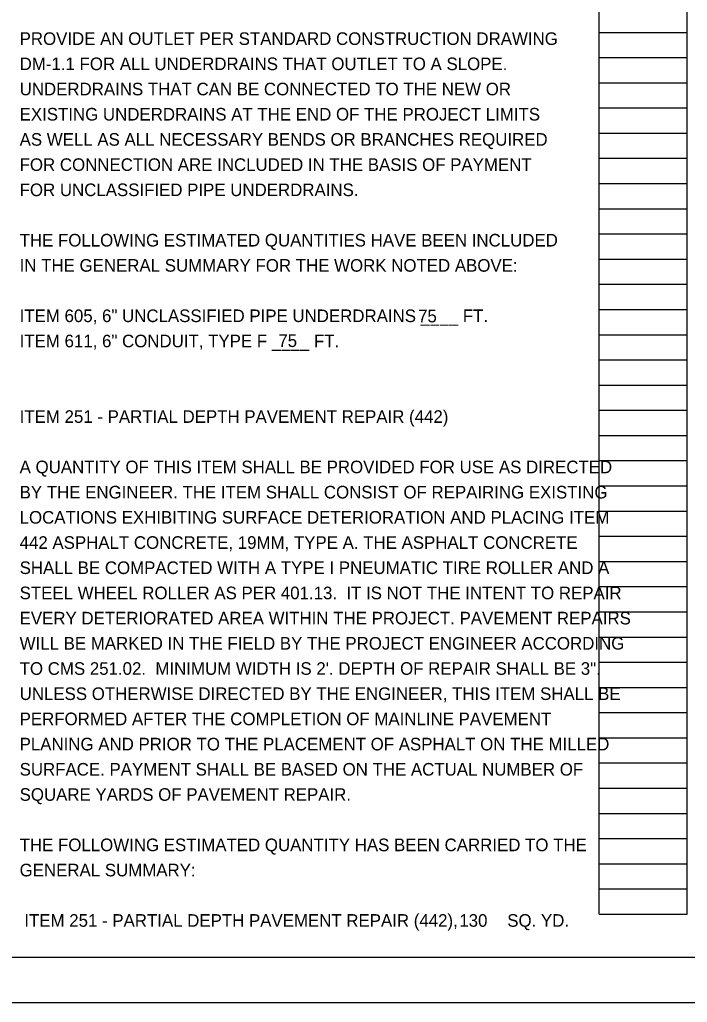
# Model space of a CAD drawing. Extents: x 0 to 74, y -27.6 to 51.8.
# Drawn here: x 17.24 to 24.66, y 0 to 10.92 of the extents above; entities that cross this region are included whole.
import ezdxf

# ---------------------------------------------------------------- set-up
doc = ezdxf.new("R2010")
doc.units = 0
for name, color, linetype in [('Level 1', 7, 'Continuous'), ('Level 2', 7, 'Continuous'), ('Level 3', 7, 'Continuous'), ('Level 4', 7, 'Continuous')]:
    doc.layers.add(name, color=color, linetype=linetype)

msp = doc.modelspace()

# ---------------------------------------------------------------- linework, layer by layer
at = {"layer": 'Level 1'}
msp.add_lwpolyline([(0, 0), (34, 0), (34, 22), (0, 22)], close=True, dxfattribs=at)
at = {"layer": 'Level 2'}
msp.add_lwpolyline([(1.5, 21.5), (33.5, 21.5), (33.5, 0.5), (1.5, 0.5)], close=True, dxfattribs=at)
at = {"layer": 'Level 3'}
for p, q in [((23.68, 0.98), (23.68, 21.14)), ((24.66, 0.98), (24.66, 21.14)), ((23.68, 10.78), (24.66, 10.78)), ((23.68, 10.5), (24.66, 10.5)), ((23.68, 10.22), (24.66, 10.22)), ((23.68, 9.94), (24.66, 9.94)), ((23.68, 9.66), (24.66, 9.66)), ((23.68, 9.38), (24.66, 9.38)), ((23.68, 9.1), (24.66, 9.1)), ((23.68, 8.82), (24.66, 8.82)), ((23.68, 8.54), (24.66, 8.54)), ((23.68, 8.26), (24.66, 8.26)), ((23.68, 7.98), (24.66, 7.98)), ((23.68, 7.7), (24.66, 7.7)), ((23.68, 7.42), (24.66, 7.42)), ((23.68, 7.14), (24.66, 7.14)), ((23.68, 6.86), (24.66, 6.86)), ((23.68, 6.58), (24.66, 6.58)), ((23.68, 6.3), (24.66, 6.3)), ((23.68, 6.02), (24.66, 6.02)), ((23.68, 5.74), (24.66, 5.74)), ((23.68, 5.46), (24.66, 5.46)), ((23.68, 5.18), (24.66, 5.18)), ((23.68, 4.9), (24.66, 4.9)), ((23.68, 4.62), (24.66, 4.62)), ((23.68, 4.34), (24.66, 4.34)), ((23.68, 4.06), (24.66, 4.06)), ((23.68, 3.78), (24.66, 3.78)), ((23.68, 3.5), (24.66, 3.5)), ((23.68, 3.22), (24.66, 3.22)), ((23.68, 2.94), (24.66, 2.94)), ((23.68, 2.66), (24.66, 2.66)), ((23.68, 2.38), (24.66, 2.38)), ((23.68, 2.1), (24.66, 2.1)), ((23.68, 1.82), (24.66, 1.82)), ((23.68, 1.54), (24.66, 1.54)), ((23.68, 1.26), (24.66, 1.26)), ((23.68, 0.98), (24.66, 0.98))]:
    msp.add_line(p, q, dxfattribs=at)

# ---------------------------------------------------------------- texts
at = {"layer": 'Level 4'}
for s, p in [('PROVIDE AN OUTLET PER STANDARD CONSTRUCTION DRAWING', (17.24, 10.64)), ('DM-1.1 FOR ALL UNDERDRAINS THAT OUTLET TO A SLOPE.', (17.24, 10.36)), ('UNDERDRAINS THAT CAN BE CONNECTED TO THE NEW OR', (17.24, 10.08)), ('EXISTING UNDERDRAINS AT THE END OF THE PROJECT LIMITS', (17.24, 9.8)), ('AS WELL AS ALL NECESSARY BENDS OR BRANCHES REQUIRED', (17.24, 9.52)), ('FOR CONNECTION ARE INCLUDED IN THE BASIS OF PAYMENT', (17.24, 9.24)), ('FOR UNCLASSIFIED PIPE UNDERDRAINS.', (17.24, 8.96)), ('THE FOLLOWING ESTIMATED QUANTITIES HAVE BEEN INCLUDED', (17.24, 8.4)), ('IN THE GENERAL SUMMARY FOR THE WORK NOTED ABOVE:', (17.24, 8.12)), ('ITEM 605, 6" UNCLASSIFIED PIPE UNDERDRAINS ____ FT.', (17.24, 7.56)), ('75', (21.668, 7.557)), ('ITEM 611, 6" CONDUIT, TYPE F ____ FT.', (17.24, 7.28)), ('75', (20.115, 7.283)), ('ITEM 251 - PARTIAL DEPTH PAVEMENT REPAIR (442)', (17.24, 6.44)), ('A QUANTITY OF THIS ITEM SHALL BE PROVIDED FOR USE AS DIRECTED ', (17.24, 5.88)), ('BY THE ENGINEER. THE ITEM SHALL CONSIST OF REPAIRING EXISTING ', (17.24, 5.6)), ('LOCATIONS EXHIBITING SURFACE DETERIORATION AND PLACING ITEM ', (17.24, 5.32)), ('442 ASPHALT CONCRETE, 19MM, TYPE A. THE ASPHALT CONCRETE ', (17.24, 5.04)), ('SHALL BE COMPACTED WITH A TYPE I PNEUMATIC TIRE ROLLER AND A ', (17.24, 4.76)), ('STEEL WHEEL ROLLER AS PER 401.13.  IT IS NOT THE INTENT TO REPAIR ', (17.24, 4.48)), ('EVERY DETERIORATED AREA WITHIN THE PROJECT. PAVEMENT REPAIRS ', (17.24, 4.2)), ('WILL BE MARKED IN THE FIELD BY THE PROJECT ENGINEER ACCORDING ', (17.24, 3.92)), ('TO CMS 251.02.  MINIMUM WIDTH IS 2\'. DEPTH OF REPAIR SHALL BE 3". ', (17.24, 3.64)), ('UNLESS OTHERWISE DIRECTED BY THE ENGINEER, THIS ITEM SHALL BE ', (17.24, 3.36)), ('PERFORMED AFTER THE COMPLETION OF MAINLINE PAVEMENT ', (17.24, 3.08)), ('PLANING AND PRIOR TO THE PLACEMENT OF ASPHALT ON THE MILLED ', (17.24, 2.8)), ('SURFACE. PAYMENT SHALL BE BASED ON THE ACTUAL NUMBER OF ', (17.24, 2.52)), ('SQUARE YARDS OF PAVEMENT REPAIR. ', (17.24, 2.24)), ('THE FOLLOWING ESTIMATED QUANTITY HAS BEEN CARRIED TO THE ', (17.24, 1.68)), ('GENERAL SUMMARY:', (17.24, 1.4)), (' ITEM 251 - PARTIAL DEPTH PAVEMENT REPAIR (442), ', (17.24, 0.84)), ('  130   ', (22.022, 0.84)), (' SQ. YD.', (22.607, 0.84))]:
    msp.add_text(s, height=0.14, dxfattribs=at).set_placement(p)

doc.saveas('drawing.dxf')
